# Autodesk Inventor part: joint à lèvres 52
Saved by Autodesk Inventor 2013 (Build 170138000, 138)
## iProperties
Created: 2012-12
Part Number: joint à lèvres 52
Material: Générique
Document SubType Name: Modeling
Designer: jost thierry
Density: 1 g/cm^3
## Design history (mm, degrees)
node "joint à lèvres 521"
node "joint à lèvres 52"
node "Base1"
